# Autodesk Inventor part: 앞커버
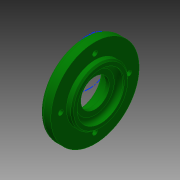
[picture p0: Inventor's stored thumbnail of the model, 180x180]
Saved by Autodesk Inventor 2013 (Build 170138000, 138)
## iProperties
Created: 2015-09
Part Number: 앞커버
Material: 알루미늄 6061
Document SubType Name: Modeling
Designer: mduedu
Density: 2.71 g/cm^3
Mass: 58.9874 g
Surface Area: 98.7754 cm^2
Volume: 21.7666 cm^3
Author: mduedu
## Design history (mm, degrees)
sketch "스케치1"
  geometry: L1 (-8, 67)-(-12, 67); L2 (-12, 67)-(-12, 78); L3 (-12, 78)-(-20, 78); L4 (-20, 78)-(-20, 66); L5 (-23, 66)-(-23, 57); L6 (-23, 57)-(-8, 57); L7 (-8, 57)-(-8, 67); L8 (-79.5, 39.5)-(-79.5, 54.5) reference; L9 (48.5, 54.5)-(48.5, 39.5) reference; L10 (-79.5, 47)-(48.5, 47); L11 (-20, 66)-(-23, 66); 3 further points
  constraints: 18 end point, 6 parallel, 4 midpoint, 1 horizontal, 1 perpendicular, 1 vertical alignment
  dimensions: "d0" = 15 distance between parallel lines of L7 L5; "d2" = 20 diameter of L6 L10; "d3" = 40 diameter of L1 L10; "d5" = 4 distance of L1.start L1.end; "d6" = 62 diameter of L3 L10; "d7" = 8 distance of L2.end L3.end; "d8" = 38 diameter of L4.end L10
revolve "회전1" sketch "스케치1" stored, may be unused: angle "d4" = 90 deg
sketch "스케치2"
  geometry: C1 r 31 at (0, 0) reference; 2 further points
  constraints: 1 coincident
hole "구멍1" sketch "스케치2" at (0, 0) diameter "d11" = 33; stored, may be unused: countersink angle "d15" = 90 deg, drill point angle "d17" = 0 deg; dims "d12" = 6, "d13" = 4, "d14" = 2, "d16" = 4
fillet "모깎기1" dims "d18" = 3
fillet "모깎기2" dims "d19" = 1, "d60" = 3
sketch "스케치3"
  geometry: C1 r 31 at (0, 0) reference; 2 further points
  constraints: 1 coincident
hole "구멍2" sketch "스케치3" at (0, 0) diameter "d20" = 30; stored, may be unused: countersink angle "d24" = 90 deg, drill point angle "d26" = 0 deg; dims "d21" = 6, "d22" = 4, "d23" = 2, "d25" = 8.3
fillet "모깎기3" dims "d27" = 0.3
chamfer "모따기1" distance "d28" = 0.8; stored, may be unused: second distance "d29" = 2, angle "d30" = 30 deg
sketch "스케치4" dims "d31" = 56
  geometry: C1 r 31 at (0, 0) reference; 6 further points
  constraints: 2 vertical alignment, 1 coincident, 7 other
  dimensions: "d36" = 360 deg dimension on C1.centre point (0, 28) (derived)
sketch "스케치7"
  geometry: C1 r 30.5 at (0, 0) reference; A1 r 24 centre (0, 0) between (24, 0) and (0, 24); 2 further points
  constraints: 4 point on circle, 2 horizontal alignment, 2 vertical alignment, 1 centre point, 1 coincident
  dimensions: "d58" = 48 diameter of A1
hole "구멍4" sketch "스케치7" at (0, 24), (-24, 0), (24, 0), (0, -24) diameter "d48" = 3.4; stored, may be unused: countersink angle "d52" = 90 deg, drill point angle "d54" = 0 deg; dims "d49" = 6, "d50" = 6.5, "d51" = 3.4, "d53" = 8
chamfer "모따기2" distance "d55" = 1; stored, may be unused: second distance "d56" = 2, angle "d57" = 45 deg
node "솔리드1"
node "참조1"
node "참조2"
node "참조3"
